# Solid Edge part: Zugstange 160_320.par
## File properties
Username: ahadarics
Dokumentum tartalom típus: 0
Author: ahadarics
Last saved by: ahadarics
Revision: 87
Sűrűség: 0,000 kg/m^3
Pontosság: 0,990
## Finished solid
Body 1: solid body, 5 faces, 7 edges, 4 vertices.
  Faces by surface: cone 2, plane 2, cylinder 1
  Edges by curve: circle 5, line 2
Bounding box of the edges (mm): 16.000 x 16.000 x 450.000, from (-8, -8, -372.5) to (8, 8, 77.5).
Cylindrical faces by radius (mm): R8 x1
Conical faces (half-angle, radius in mm at the cone's reference point): 45 deg R7.5 x2
Planar faces by outward normal: +z 1, -z 1
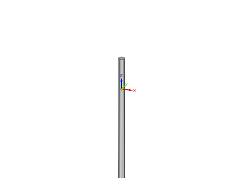
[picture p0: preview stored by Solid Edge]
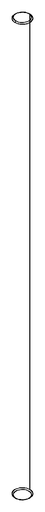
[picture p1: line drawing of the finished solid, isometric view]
